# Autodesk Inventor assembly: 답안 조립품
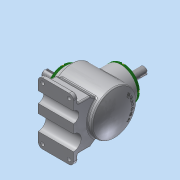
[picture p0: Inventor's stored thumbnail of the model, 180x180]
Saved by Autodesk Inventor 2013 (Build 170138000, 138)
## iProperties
Created: 2018-08
Part Number: 답안 조립품
Document SubType Name: Assembly
Designer: Administrator
Author: Administrator
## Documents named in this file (14)
- C:\Users\Administrator\Desktop\480808V1013\답안 조립품.iam
- C:\Users\Administrator\Desktop\480808V1013\베어링 6203.ipt
- C:\Users\Administrator\Desktop\480808V1013\본체.ipt
- C:\Users\Administrator\Desktop\480808V1013\볼트 M4.ipt
- C:\Users\Administrator\Desktop\480808V1013\서브 베벨기어.ipt
- C:\Users\Administrator\Desktop\480808V1013\서브 축.ipt
- 서브 축.ipt
- C:\Users\Administrator\Desktop\480808V1013\오일실 17 32 8.ipt
- C:\Users\Administrator\Desktop\480808V1013\커버.ipt
- C:\Users\Administrator\Desktop\480808V1013\키 4x4.ipt
- C:\Users\Administrator\Desktop\480808V1013\키 5x5.ipt
- C:\Users\Administrator\Desktop\480808V1013\메인 베벨기어.ipt
- C:\Users\Administrator\Desktop\480808V1013\메인 축.ipt
- 메인 축.ipt
